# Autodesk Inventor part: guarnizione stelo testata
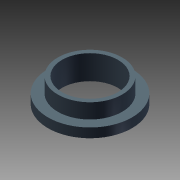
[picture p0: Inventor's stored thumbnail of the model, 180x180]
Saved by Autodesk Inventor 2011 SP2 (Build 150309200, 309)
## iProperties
Created: 2018-03
Part Number: guarnizione stelo testata
Document SubType Name: Modeling
Designer: 18619647
Density: 1 g/cm^3
Author: 18619647
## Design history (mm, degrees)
sketch "Schizzo1"
  geometry: C1 r 9 at (0, 0); C2 r 6 at (0, 0); 1 further point
  constraints: 2 centre point, 2 coincident
  dimensions: "d0" = 18 diameter of C1; "d1" = 12 diameter of C2
extrude "Estrusione1" new body sketch "Schizzo1" distance "d2" = 2; taper "d3" = 0 deg
sketch "Schizzo2"
  geometry: C1 r 6 at (0, 0) reference; C2 r 9 at (0, 0) reference; C3 r 6.9 at (0, 0)
  constraints: 1 centre point, 1 coincident
  dimensions: "d4" = 13.8 diameter of C3
extrude "Estrusione2" join sketch "Schizzo2" distance "d5" = 3.2; taper "d6" = 0 deg
node "Solido1"
